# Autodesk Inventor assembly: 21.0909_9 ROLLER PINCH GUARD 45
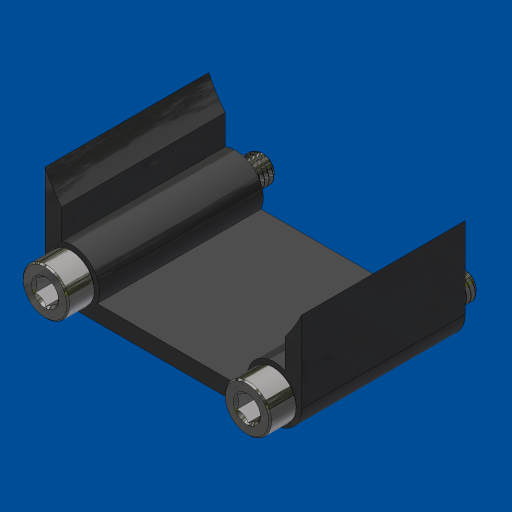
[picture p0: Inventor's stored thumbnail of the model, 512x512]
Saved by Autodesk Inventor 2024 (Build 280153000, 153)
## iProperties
Created: 2025-01
Part Number: 21.0909_9 ROLLER PINCH GUARD 45
Document SubType Name: Assembly
Designer: amoles
Author: amoles
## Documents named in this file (3)
- L:\INVENTOR LIBRARIES\PARTS LIBRARY\BELT AND ROLLER CONVEYORS\21.0909_9 ROLLER PINCH GUARD 45.iam
- L:\INVENTOR LIBRARIES\PARTS LIBRARY\BELT AND ROLLER CONVEYORS\SUBCOMPONENTS\21.0909_9 PLASTIC SHEILD.ipt
- L:\INVENTOR LIBRARIES\PARTS LIBRARY\FASTENING ELEMENTS\SCREWS CAP\21.2195 M5X35 SS HH.ipt
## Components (3 placed, 2 different names)
1. 21.0909_9 PLASTIC SHEILD:1 — Mate:1, Mate:2, Flush:1, Insert:1, Insert:2
2. 21.2195 M5X35 SS HH:1 — Insert:1
3. 21.2195 M5X35 SS HH:2 — Insert:2
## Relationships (5: Mate 2, Insert 2, Flush 1)
- Mate:1: 21.0909_9 PLASTIC SHEILD:1
- Mate:2: 21.0909_9 PLASTIC SHEILD:1
- Flush:1: 21.0909_9 PLASTIC SHEILD:1
- Insert:1: 21.0909_9 PLASTIC SHEILD:1 ↔ 21.2195 M5X35 SS HH:1
- Insert:2: 21.0909_9 PLASTIC SHEILD:1 ↔ 21.2195 M5X35 SS HH:2
